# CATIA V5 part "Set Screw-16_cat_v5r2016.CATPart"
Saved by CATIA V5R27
Part number: Set Screw-16
Bounding box of the stored display mesh (mm): x -5.916 to 5.916, y -5.992 to 5.992, z -1.443 to 23
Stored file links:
  E:\_Deepak\2017_Deepak\CATIA\Resources\Tutorial Files\Tutorials\c13_catia_v5_6r2016_tut\c13tut2\c13tut02.CATParts\Set Screw-16_cat_v5r2016.CATPart
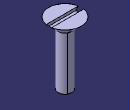
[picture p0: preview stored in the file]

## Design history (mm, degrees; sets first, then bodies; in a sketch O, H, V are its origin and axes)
Body1 (main body)
  Sketch1 on yz-plane, origin (0, 0, 0), H (0, 1, 0), V (0, 0, 1)
    point P1 (0, -1.4434)
    line L1 (0, -1.4434) -> (2.5, 0)
    point P2 (2.5, 0)
    line L2 (2.5, 0) -> (2.5, 19.5)
    line L3 (2.5, 19.5) -> (6, 23)
    point P4 (6, 23)
    line L4 (6, 23) -> (0, 23)
    point P5 (0, 23)
    line L5 (0, 23) -> (0, -1.4434)
    length L2 = 19.5
    distance L2 L5 = 2.5
    distance P4 L5 = 6
    angle L3 L5 = 45
    angle L5 L1 = 60
    coincidence: P1 V, P2 H, P5 V
    vertical: L2 V, L5 V
    horizontal: L4 H
  Shaft1: profile Sketch1, axis edge of Sketch1, angle 360
  Sketch2 on yz-plane, origin (0, 0, 0), H (0, 1, 0), V (0, 0, 1)
    line L1 (-1, 23) -> (1, 23)
    line L2 (1, 23) -> (1, 22)
    line L3 (1, 22) -> (-1, 22)
    line L4 (-1, 22) -> (-1, 23)
    reference projected line E1 (6, 23) -> (-6, 23) from edge of Shaft1
    distance V L2 = 1
    length L1 = 2
    length L2 = 1
    horizontal: L1 H, L3 H
    vertical: L2 V, L4 V
    coincidence: L1 E1
  Pocket1: profile Sketch2, direction (-1, 0, 0), length 16, mirrored extent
